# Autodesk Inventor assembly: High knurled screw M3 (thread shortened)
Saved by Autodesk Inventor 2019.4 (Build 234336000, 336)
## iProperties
Created: 2021-08
Part Number: High knurled screw M3 (thread shortened)
Document SubType Name: Assembly
Designer: Administrator
Title: High knurled screw M3 (thread shortened) v6
Author: Administrator
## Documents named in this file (2)
- c:\worker\convert-fusion-r06\tmp\job-1\20\output\files\f01db8e3-9ba6-469c-91a4-18b8ab1b818d\High knurled screw M3 (thread shortened) v6.iam
- c:\worker\convert-fusion-r06\tmp\job-1\20\output\files\f01db8e3-9ba6-469c-91a4-18b8ab1b818d\_Knurled screw DIN 464-M3-6-ZB.ipt
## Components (1 placed, 1 different names)
1. _Knurled screw DIN 464-M3-6-ZB:1
